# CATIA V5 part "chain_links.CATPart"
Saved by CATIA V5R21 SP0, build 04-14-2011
Part number: chain_links
Bounding box of the stored display mesh (mm): x -25 to 25, y -25 to 105, z -35 to 15
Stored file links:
  C:\Users\swlee\Desktop\chain_links.CATPart
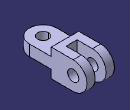
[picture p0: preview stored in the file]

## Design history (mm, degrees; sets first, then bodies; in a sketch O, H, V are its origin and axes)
AxisSystem1: origin (0, 0, 0), X (1, 0, 0), Y (0, 1, 0), Z (0, 0, 1)
Body1 (main body)
  DatumSurface1
  Sketch1 on XY plane of AxisSystem1, origin (0, 0, 0), H (1, 0, 0), V (0, 1, 0)
    circle A1 centre (0, 0) radius 10
    arc A2 centre (0, 0) radius 25 from (-25, 0) to (25, 0) ccw
    point P1 (-25, 0)
    line L1 (-25, 0) -> (-25, 40)
    point P3 (25, 0)
    line L2 (25, 0) -> (25, 40)
    line L3 (-25, 40) -> (25, 40)
    point P5 (-25, 0)
    point P6 (25, 0)
    reference projected line E1 through (0, 0) direction (1, 0) from edge [XY plane of AxisSystem1 | ZX plane of AxisSystem1]
    radius A2 = 25
    distance L3 E1 = 40
    fix: A1
    coincidence: P1 A2, P1 H, P3 A2, P3 H, L2 P6, L1 P5, P1 P5, P3 P6
    tangency: L1 A2, L2 A2
    horizontal: L3 H
  Pad1: profile Sketch1, direction (0, 0, -1), length 20
  Sketch2 on face of Pad1 from Sketch1.L2, origin (25, 0, 0), H (0, 1, 0), V (0, 0, 1)
    arc A1 centre (80, -10) radius 25 from (80, -35) to (80, 15) ccw
    point P1 (80, -10)
    reference intersected line E1 through (0, 0) direction (-1, 0) from XY plane of AxisSystem1
    reference projected line E2 (40, 0) -> (40, -20) from edge [face of Pad1 from Sketch1.L2 | face of Pad1 from Sketch1.L3]
    line L1 (80, 15) -> (40, 15)
    line L2 (80, -35) -> (40, -35)
    line L3 (40, 15) -> (40, -35)
    reference projected line E3 (40, 0) -> (40, -20) from edge [face of Pad1 from Sketch1.L2 | face of Pad1 from Sketch1.L3]
    distance P1 E1 = 10
    distance E2 P1 = 40 {= Sketch1.distance(L3 E1)}
    radius A1 = 25
    tangency: L1 A1, L2 A1
    vertical: L3 V
    coincidence: L3 E3
    horizontal: L2 H, L1 H
  Pad2: profile Sketch2, direction (-1, 0, 0), up to face of Pad1 from Sketch1.L1
  Sketch3 on face of Pad2 from Sketch2.L1, origin (0, 0, 15), H (1, 0, 0), V (0, 1, 0)
    line L1 (-10, 111.8548) -> (10, 111.8548)
    line L2 (10, 111.8548) -> (10, 52)
    line L3 (10, 52) -> (-10, 52)
    line L4 (-10, 52) -> (-10, 111.8548)
    reference projected line E1 through (0, 0) direction (0, 1) from edge [YZ plane of AxisSystem1 | XY plane of AxisSystem1]
    reference projected line E2 (25, 80) -> (-25, 80) from edge [face of Pad2 from Sketch2.A1 | face of Pad2 from Sketch2.L1]
    distance L3 E2 = 28
    distance L4 L2 = 20
    horizontal: L1 H, L3 H
    vertical: L2 V, L4 V
    symmetry: L2 L4 E1
  Pocket1: profile Sketch3, direction (0, 0, -1), through (limit type 3)
  Sketch4 on face of Pad1, origin (25, 94.7509, 0.2628), H (0, 1, 0), V (0, 0, 1)
    point P1 (-14.7509, -10.2628)
    reference projected arc E1 centre (-14.7509, -10.2628) radius 25 from (-14.7509, -35.2628) to (-14.7509, 14.7372) ccw from edge [face of Pad2 from Sketch2.A1 | start face of Pad2]
    concentricity: E1 P1
  Hole1: placed by Sketch4, at (25, 80, -10) direction (-1, 0, 0), diameter 20, through (limit type 3)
